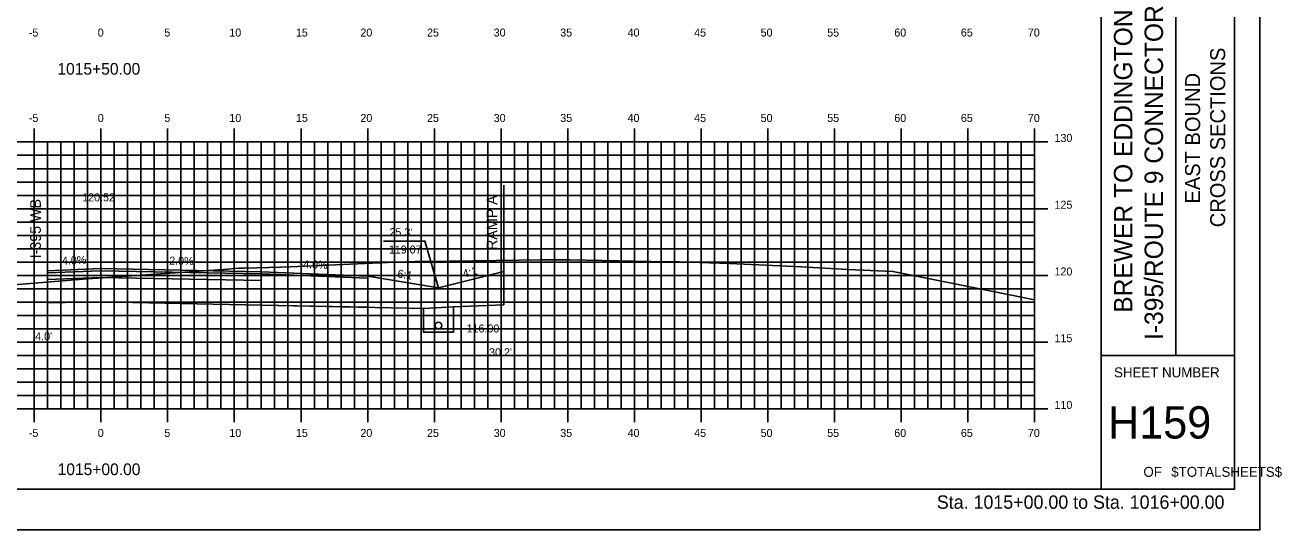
# Model space of a CAD drawing. Extents: x 853069 to 853241, y 365624 to 365734.
# Drawn here: x 853146.4 to 853240.6, y 365624 to 365661.8 of the extents above; entities that cross this region are included whole.
import ezdxf

# ---------------------------------------------------------------- set-up
doc = ezdxf.new("R2010")
doc.units = 0
for name, color, linetype in [('ANNOTATION', 7, 'Continuous'), ('BORDER', 7, 'Continuous'), ('D_Roadway_Centerline', 7, 'Continuous'), ('D_Roadway_Centerline_Text', 7, 'Continuous'), ('D_Roadway_Edge_Shoulder', 7, 'Continuous'), ('D_Roadway_Edge_TW', 7, 'Continuous'), ('D_Roadway_FinishedGrade', 7, 'Continuous'), ('D_Roadway_Pavement', 7, 'Continuous'), ('D_Roadway_SubGrade', 7, 'Continuous'), ('D_Text_Standard', 7, 'Continuous'), ('H_V ANNOTATION', 7, 'Continuous'), ('M_Roadway_Centerline', 7, 'Continuous'), ('MAJOR', 7, 'Continuous'), ('MINOR', 7, 'Continuous'), ('PDRAIN', 7, 'Continuous'), ('PLOT BOUNDARY', 7, 'Continuous'), ('S_Roadway_Centerline', 7, 'Continuous')]:
    doc.layers.add(name, color=color, linetype=linetype)

msp = doc.modelspace()

# ---------------------------------------------------------------- linework, layer by layer
at = {"layer": 'ANNOTATION'}
msp.add_lwpolyline([(853173.241, 365645.607), (853176.35, 365645.607), (853177.361, 365642.101)], dxfattribs=at)
at = {"layer": 'BORDER'}
for p, q in [((853227.062, 365627.027), (853227.062, 365732.027)), ((853232.653, 365637.03), (853232.653, 365672.03)), ((853227.062, 365637.03), (853237.062, 365637.03))]:
    msp.add_line(p, q, dxfattribs=at)
msp.add_lwpolyline([(853077.062, 365627.027), (853237.062, 365627.027), (853237.062, 365732.027), (853077.062, 365732.027)], close=True, dxfattribs=at)
at = {"layer": 'D_Roadway_Centerline'}
for p, q in [((853172.061, 365642.985), (853177.361, 365642.101)), ((853182.281, 365643.33), (853182.281, 365640.83)), ((853164.062, 365640.805), (853176.236, 365640.561)), ((853176.236, 365640.561), (853178.486, 365640.679))]:
    msp.add_line(p, q, dxfattribs=at)
for points in [[(853148.061, 365643.385), (853152.062, 365643.545), (853152.063, 365643.545), (853164.062, 365643.305), (853172.061, 365642.985)], [(853177.361, 365642.101), (853178.472, 365642.379), (853182.281, 365643.33)], [(853182.281, 365640.83), (853178.486, 365640.679)]]:
    msp.add_lwpolyline(points, dxfattribs=at)
at = {"layer": 'D_Roadway_Edge_Shoulder'}
for points in [[(853152.062, 365643.545), (853148.061, 365643.385), (853148.061, 365643.218), (853152.062, 365643.378)], [(853164.062, 365643.305), (853172.061, 365642.985), (853172.061, 365642.818), (853164.062, 365643.138)]]:
    msp.add_lwpolyline(points, close=True, dxfattribs=at)
at = {"layer": 'D_Roadway_Edge_TW'}
msp.add_lwpolyline([(853152.062, 365643.545), (853164.062, 365643.305), (853164.062, 365643.138), (853152.062, 365643.378)], close=True, dxfattribs=at)
msp.add_lwpolyline([(853164.062, 365643.305), (853164.062, 365643.138)], dxfattribs=at)
at = {"layer": 'D_Roadway_FinishedGrade'}
for p, q in [((853148.061, 365643.385), (853148.061, 365643.135)), ((853152.062, 365643.545), (853152.062, 365643.295)), ((853164.062, 365643.305), (853164.062, 365643.055)), ((853172.061, 365642.985), (853172.061, 365642.735))]:
    msp.add_line(p, q, dxfattribs=at)
at = {"layer": 'D_Roadway_Pavement'}
for points in [[(853152.062, 365643.378), (853148.061, 365643.218), (853148.061, 365642.718), (853152.062, 365642.878)], [(853152.062, 365643.378), (853164.062, 365643.138), (853164.062, 365642.638), (853152.062, 365642.878)]]:
    msp.add_lwpolyline(points, close=True, dxfattribs=at)
msp.add_lwpolyline([(853164.062, 365643.138), (853164.062, 365642.638)], dxfattribs=at)
msp.add_lwpolyline([(853164.062, 365643.138), (853164.062, 365642.638)], dxfattribs=at)
at = {"layer": 'D_Roadway_SubGrade'}
for p, q in [((853148.061, 365649.289), (853148.061, 365640.965)), ((853182.281, 365649.792), (853182.281, 365640.83))]:
    msp.add_line(p, q, dxfattribs=at)
for points in [[(853152.062, 365642.878), (853148.061, 365642.718), (853148.061, 365643.218), (853148.061, 365643.385), (853148.061, 365640.965), (853152.062, 365641.045)], [(853152.062, 365642.878), (853164.062, 365642.638), (853164.062, 365640.805), (853152.062, 365641.045)], [(853164.062, 365642.638), (853164.062, 365643.138), (853172.061, 365642.818), (853172.061, 365642.985), (853172.061, 365640.645), (853164.062, 365640.805)]]:
    msp.add_lwpolyline(points, close=True, dxfattribs=at)
msp.add_lwpolyline([(853164.062, 365642.638), (853164.062, 365640.805)], dxfattribs=at)
at = {"layer": 'MAJOR'}
for p, q in [((853147.061, 365654.029), (853147.061, 365653.027)), ((853152.061, 365654.029), (853152.061, 365653.027)), ((853157.061, 365654.029), (853157.061, 365653.027)), ((853162.061, 365654.029), (853162.061, 365653.027)), ((853167.061, 365654.029), (853167.061, 365653.027)), ((853172.061, 365654.029), (853172.061, 365653.027)), ((853177.061, 365654.029), (853177.061, 365653.027)), ((853182.061, 365654.029), (853182.061, 365653.027)), ((853187.061, 365654.029), (853187.061, 365653.027)), ((853192.061, 365654.029), (853192.061, 365653.027)), ((853197.061, 365654.029), (853197.061, 365653.027)), ((853202.061, 365654.029), (853202.061, 365653.027)), ((853207.061, 365654.029), (853207.061, 365653.027)), ((853212.061, 365654.029), (853212.061, 365653.027)), ((853217.061, 365654.029), (853217.061, 365653.027)), ((853222.061, 365654.029), (853222.061, 365653.027)), ((853082.061, 365653.027), (853222.061, 365653.027)), ((853082.061, 365653.027), (853222.061, 365653.027)), ((853147.061, 365633.027), (853147.061, 365653.027)), ((853152.061, 365633.027), (853152.061, 365653.027)), ((853157.061, 365633.027), (853157.061, 365653.027)), ((853162.061, 365633.027), (853162.061, 365653.027)), ((853167.061, 365633.027), (853167.061, 365653.027)), ((853172.061, 365633.027), (853172.061, 365653.027)), ((853177.061, 365633.027), (853177.061, 365653.027)), ((853182.061, 365633.027), (853182.061, 365653.027)), ((853187.061, 365633.027), (853187.061, 365653.027)), ((853192.061, 365633.027), (853192.061, 365653.027)), ((853197.061, 365633.027), (853197.061, 365653.027)), ((853202.061, 365633.027), (853202.061, 365653.027)), ((853207.061, 365633.027), (853207.061, 365653.027)), ((853212.061, 365633.027), (853212.061, 365653.027)), ((853217.061, 365633.027), (853217.061, 365653.027)), ((853223.063, 365653.027), (853221.059, 365653.027)), ((853222.061, 365633.027), (853222.061, 365653.027)), ((853222.061, 365633.027), (853222.061, 365653.027)), ((853082.061, 365648.027), (853222.061, 365648.027)), ((853223.063, 365648.027), (853221.059, 365648.027)), ((853082.061, 365643.027), (853222.061, 365643.027)), ((853223.063, 365643.027), (853221.059, 365643.027)), ((853082.061, 365638.027), (853222.061, 365638.027)), ((853223.063, 365638.027), (853221.059, 365638.027)), ((853082.061, 365633.027), (853222.061, 365633.027)), ((853082.061, 365633.027), (853222.061, 365633.027)), ((853147.061, 365632.025), (853147.061, 365633.027)), ((853152.061, 365632.025), (853152.061, 365633.027)), ((853157.061, 365632.025), (853157.061, 365633.027)), ((853162.061, 365632.025), (853162.061, 365633.027)), ((853167.061, 365632.025), (853167.061, 365633.027)), ((853172.061, 365632.025), (853172.061, 365633.027)), ((853177.061, 365632.025), (853177.061, 365633.027)), ((853182.061, 365632.025), (853182.061, 365633.027)), ((853187.061, 365632.025), (853187.061, 365633.027)), ((853192.061, 365632.025), (853192.061, 365633.027)), ((853197.061, 365632.025), (853197.061, 365633.027)), ((853202.061, 365632.025), (853202.061, 365633.027)), ((853207.061, 365632.025), (853207.061, 365633.027)), ((853212.061, 365632.025), (853212.061, 365633.027)), ((853217.061, 365632.025), (853217.061, 365633.027)), ((853223.063, 365633.027), (853221.059, 365633.027)), ((853222.061, 365632.025), (853222.061, 365633.027))]:
    msp.add_line(p, q, dxfattribs=at)
at = {"layer": 'MINOR'}
for p, q in [((853148.061, 365633.027), (853148.061, 365653.027)), ((853149.061, 365633.027), (853149.061, 365653.027)), ((853150.061, 365633.027), (853150.061, 365653.027)), ((853151.061, 365633.027), (853151.061, 365653.027)), ((853153.061, 365633.027), (853153.061, 365653.027)), ((853154.061, 365633.027), (853154.061, 365653.027)), ((853155.061, 365633.027), (853155.061, 365653.027)), ((853156.061, 365633.027), (853156.061, 365653.027)), ((853158.061, 365633.027), (853158.061, 365653.027)), ((853159.061, 365633.027), (853159.061, 365653.027)), ((853160.061, 365633.027), (853160.061, 365653.027)), ((853161.061, 365633.027), (853161.061, 365653.027)), ((853163.061, 365633.027), (853163.061, 365653.027)), ((853164.061, 365633.027), (853164.061, 365653.027)), ((853165.061, 365633.027), (853165.061, 365653.027)), ((853166.061, 365633.027), (853166.061, 365653.027)), ((853168.061, 365633.027), (853168.061, 365653.027)), ((853169.061, 365633.027), (853169.061, 365653.027)), ((853170.061, 365633.027), (853170.061, 365653.027)), ((853171.061, 365633.027), (853171.061, 365653.027)), ((853173.061, 365633.027), (853173.061, 365653.027)), ((853174.061, 365633.027), (853174.061, 365653.027)), ((853175.061, 365633.027), (853175.061, 365653.027)), ((853176.061, 365633.027), (853176.061, 365653.027)), ((853178.061, 365633.027), (853178.061, 365653.027)), ((853179.061, 365633.027), (853179.061, 365653.027)), ((853180.061, 365633.027), (853180.061, 365653.027)), ((853181.061, 365633.027), (853181.061, 365653.027)), ((853183.061, 365633.027), (853183.061, 365653.027)), ((853184.061, 365633.027), (853184.061, 365653.027)), ((853185.061, 365633.027), (853185.061, 365653.027)), ((853186.061, 365633.027), (853186.061, 365653.027)), ((853188.061, 365633.027), (853188.061, 365653.027)), ((853189.061, 365633.027), (853189.061, 365653.027)), ((853190.061, 365633.027), (853190.061, 365653.027)), ((853191.061, 365633.027), (853191.061, 365653.027)), ((853193.061, 365633.027), (853193.061, 365653.027)), ((853194.061, 365633.027), (853194.061, 365653.027)), ((853195.061, 365633.027), (853195.061, 365653.027)), ((853196.061, 365633.027), (853196.061, 365653.027)), ((853198.061, 365633.027), (853198.061, 365653.027)), ((853199.061, 365633.027), (853199.061, 365653.027)), ((853200.061, 365633.027), (853200.061, 365653.027)), ((853201.061, 365633.027), (853201.061, 365653.027)), ((853203.061, 365633.027), (853203.061, 365653.027)), ((853204.061, 365633.027), (853204.061, 365653.027)), ((853205.061, 365633.027), (853205.061, 365653.027)), ((853206.061, 365633.027), (853206.061, 365653.027)), ((853208.061, 365633.027), (853208.061, 365653.027)), ((853209.061, 365633.027), (853209.061, 365653.027)), ((853210.061, 365633.027), (853210.061, 365653.027)), ((853211.061, 365633.027), (853211.061, 365653.027)), ((853213.061, 365633.027), (853213.061, 365653.027)), ((853214.061, 365633.027), (853214.061, 365653.027)), ((853215.061, 365633.027), (853215.061, 365653.027)), ((853216.061, 365633.027), (853216.061, 365653.027)), ((853218.061, 365633.027), (853218.061, 365653.027)), ((853219.061, 365633.027), (853219.061, 365653.027)), ((853220.061, 365633.027), (853220.061, 365653.027)), ((853221.061, 365633.027), (853221.061, 365653.027)), ((853082.061, 365652.027), (853222.061, 365652.027)), ((853222.061, 365652.027), (853221.059, 365652.027)), ((853082.061, 365651.027), (853222.061, 365651.027)), ((853222.061, 365651.027), (853221.059, 365651.027)), ((853082.061, 365650.027), (853222.061, 365650.027)), ((853222.061, 365650.027), (853221.059, 365650.027)), ((853082.061, 365649.027), (853222.061, 365649.027)), ((853222.061, 365649.027), (853221.059, 365649.027)), ((853082.061, 365647.027), (853222.061, 365647.027)), ((853222.061, 365647.027), (853221.059, 365647.027)), ((853082.061, 365646.027), (853222.061, 365646.027)), ((853222.061, 365646.027), (853221.059, 365646.027)), ((853082.061, 365645.027), (853222.061, 365645.027)), ((853222.061, 365645.027), (853221.059, 365645.027)), ((853082.061, 365644.027), (853222.061, 365644.027)), ((853222.061, 365644.027), (853221.059, 365644.027)), ((853082.061, 365642.027), (853222.061, 365642.027)), ((853222.061, 365642.027), (853221.059, 365642.027)), ((853082.061, 365641.027), (853222.061, 365641.027)), ((853222.061, 365641.027), (853221.059, 365641.027)), ((853082.061, 365640.027), (853222.061, 365640.027)), ((853222.061, 365640.027), (853221.059, 365640.027)), ((853082.061, 365639.027), (853222.061, 365639.027)), ((853222.061, 365639.027), (853221.059, 365639.027)), ((853082.061, 365637.027), (853222.061, 365637.027)), ((853222.061, 365637.027), (853221.059, 365637.027)), ((853082.061, 365636.027), (853222.061, 365636.027)), ((853222.061, 365636.027), (853221.059, 365636.027)), ((853082.061, 365635.027), (853222.061, 365635.027)), ((853222.061, 365635.027), (853221.059, 365635.027)), ((853082.061, 365634.027), (853222.061, 365634.027)), ((853222.061, 365634.027), (853221.059, 365634.027))]:
    msp.add_line(p, q, dxfattribs=at)
at = {"layer": 'PDRAIN'}
msp.add_lwpolyline([(853176.236, 365640.561), (853176.236, 365638.771), (853178.486, 365638.771), (853178.486, 365640.679)], dxfattribs=at)
msp.add_circle((853177.361, 365639.271), 0.25, dxfattribs=at)
at = {"layer": 'PLOT BOUNDARY'}
msp.add_lwpolyline([(853068.968, 365623.968), (853238.968, 365623.968), (853238.968, 365733.968), (853068.968, 365733.968)], close=True, dxfattribs=at)
at = {"layer": 'S_Roadway_Centerline'}
msp.add_lwpolyline([(853145.525, 365642.331), (853150.736, 365642.756), (853161.248, 365643.464), (853162.416, 365643.572), (853162.827, 365643.566), (853165.563, 365643.643), (853166.278, 365643.683), (853173.552, 365643.992), (853176.273, 365644.097), (853176.504, 365644.062), (853185.133, 365644.203), (853187.226, 365644.206), (853194.515, 365644.047), (853194.679, 365644.073), (853199.221, 365643.919), (853204.577, 365643.667), (853208.089, 365643.485), (853211.445, 365643.323), (853212.077, 365643.209), (853219.577, 365641.693), (853222.061, 365641.208)], dxfattribs=at)

# ---------------------------------------------------------------- texts
at = {"layer": 'ANNOTATION'}
for s, height, rotation, p in [('I-395 WB', 0.8, 90, (853147.554, 365644.303)), ('RAMP A', 0.8, 90, (853181.774, 365644.932)), ("25.3' ", 0.6, 360, (853173.694, 365645.97)), ('119.07', 0.6, 360, (853173.649, 365644.67)), ('-4.0%', 0.6, 2.29042, (853148.878, 365643.818)), ('-2.0%', 0.6, 358.85424, (853156.905, 365643.848)), ('-4.0%', 0.6, 357.70931, (853166.957, 365643.59)), ('4:1', 0.6, 14.02221, (853179.267, 365642.852)), ('6:1', 0.6, 350.53768, (853174.257, 365642.889))]:
    msp.add_text(s, height=height, rotation=rotation, dxfattribs=at).set_placement(p)
at = {"layer": 'BORDER'}
for s, height, p in [('BREWER TO EDDINGTON', 1.37787, (853229.395, 365640.231)), ('I-395/ROUTE 9 CONNECTOR', 1.37787, (853231.696, 365638.192)), ('CROSS SECTIONS', 1.125, (853236.359, 365646.638)), ('EAST BOUND', 1.125, (853234.48, 365648.418))]:
    msp.add_text(s, height=height, rotation=90, dxfattribs=at).set_placement(p)
for s, height, p in [('SHEET NUMBER', 0.74527, (853228.027, 365635.393)), ('H159', 2.4194, (853227.577, 365630.809)), ('OF', 0.7453, (853230.229, 365627.94)), ('$TOTALSHEETS$', 0.74527, (853232.318, 365627.94))]:
    msp.add_text(s, height=height, dxfattribs=at).set_placement(p)
at = {"layer": 'D_Roadway_Centerline'}
for s, p in [('C', (853152.056, 365643.545)), ('L', (853152.062, 365643.537))]:
    msp.add_text(s, height=0.0146, dxfattribs=at).set_placement(p)
at = {"layer": 'D_Roadway_Centerline_Text'}
msp.add_text('120.52', height=0.6, dxfattribs=at).set_placement((853150.651, 365648.577))
at = {"layer": 'D_Text_Standard'}
for s, p in [('116.00', (853179.476, 365638.756)), ("4.0'", (853147.128, 365638.171)), ("30.2'", (853181.165, 365636.974))]:
    msp.add_text(s, height=0.6, dxfattribs=at).set_placement(p)
at = {"layer": 'H_V ANNOTATION'}
for s, height, p in [('-5', 0.6, (853146.652, 365660.927)), ('0', 0.6, (853151.821, 365660.927)), ('5', 0.6, (853156.813, 365660.927)), ('10', 0.6, (853161.687, 365660.927)), ('15', 0.6, (853166.679, 365660.927)), ('20', 0.6, (853171.515, 365660.927)), ('25', 0.6, (853176.507, 365660.927)), ('30', 0.6, (853181.51, 365660.927)), ('35', 0.6, (853186.502, 365660.927)), ('40', 0.6, (853191.548, 365660.927)), ('45', 0.6, (853196.54, 365660.927)), ('50', 0.6, (853201.526, 365660.927)), ('55', 0.6, (853206.518, 365660.927)), ('60', 0.6, (853211.548, 365660.927)), ('65', 0.6, (853216.54, 365660.927)), ('70', 0.6, (853221.564, 365660.927)), ('1015+50.00', 0.875, (853148.792, 365658.07)), ('-5', 0.6, (853146.652, 365654.527)), ('0', 0.6, (853151.821, 365654.527)), ('5', 0.6, (853156.813, 365654.527)), ('10', 0.6, (853161.687, 365654.527)), ('15', 0.6, (853166.679, 365654.527)), ('20', 0.6, (853171.515, 365654.527)), ('25', 0.6, (853176.507, 365654.527)), ('30', 0.6, (853181.51, 365654.527)), ('35', 0.6, (853186.502, 365654.527)), ('40', 0.6, (853191.548, 365654.527)), ('45', 0.6, (853196.54, 365654.527)), ('50', 0.6, (853201.526, 365654.527)), ('55', 0.6, (853206.518, 365654.527)), ('60', 0.6, (853211.548, 365654.527)), ('65', 0.6, (853216.54, 365654.527)), ('70', 0.6, (853221.564, 365654.527)), ('130', 0.6, (853223.561, 365653.027)), ('125', 0.6, (853223.561, 365648.027)), ('120', 0.6, (853223.561, 365643.027)), ('115', 0.6, (853223.561, 365638.027)), ('110', 0.6, (853223.561, 365633.027)), ('-5', 0.6, (853146.652, 365630.927)), ('0', 0.6, (853151.821, 365630.927)), ('5', 0.6, (853156.813, 365630.927)), ('10', 0.6, (853161.687, 365630.927)), ('15', 0.6, (853166.679, 365630.927)), ('20', 0.6, (853171.515, 365630.927)), ('25', 0.6, (853176.507, 365630.927)), ('30', 0.6, (853181.51, 365630.927)), ('35', 0.6, (853186.502, 365630.927)), ('40', 0.6, (853191.548, 365630.927)), ('45', 0.6, (853196.54, 365630.927)), ('50', 0.6, (853201.526, 365630.927)), ('55', 0.6, (853206.518, 365630.927)), ('60', 0.6, (853211.548, 365630.927)), ('65', 0.6, (853216.54, 365630.927)), ('70', 0.6, (853221.564, 365630.927)), ('1015+00.00', 0.875, (853148.808, 365628.07)), ('Sta. 1015+00.00 to Sta. 1016+00.00', 1.0002, (853214.738, 365625.547))]:
    msp.add_text(s, height=height, dxfattribs=at).set_placement(p)
at = {"layer": 'M_Roadway_Centerline'}
for s, p in [('C', (853176.268, 365644.097)), ('L', (853176.273, 365644.09)), ('C', (853194.674, 365644.073)), ('L', (853194.679, 365644.066))]:
    msp.add_text(s, height=0.0146, dxfattribs=at).set_placement(p)

doc.saveas('drawing.dxf')
